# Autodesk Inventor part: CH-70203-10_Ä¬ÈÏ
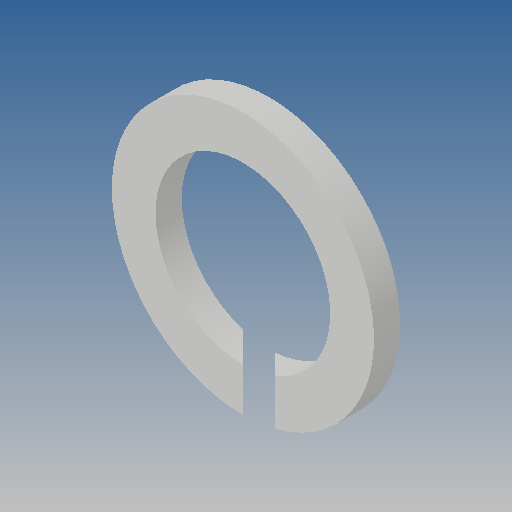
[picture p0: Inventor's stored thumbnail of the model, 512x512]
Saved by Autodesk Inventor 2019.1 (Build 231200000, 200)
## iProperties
Created: 2010-06
Part Number: CH-70203-10_Ä¬ÈÏ
Material: Ogólny
Document SubType Name: Modeling
Designer: CADENGINEERING4
Density: 1 g/cm^3
Appearance: Domyślna
Author: CADENGINEERING4
Revision Number: ÈÎºÎ
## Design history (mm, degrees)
feature "NONE"
node "Bryła1"
